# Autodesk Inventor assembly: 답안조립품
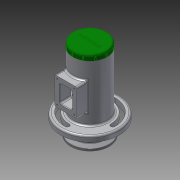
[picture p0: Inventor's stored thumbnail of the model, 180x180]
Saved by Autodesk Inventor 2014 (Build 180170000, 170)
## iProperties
Created: 2017-05
Part Number: 답안조립품
Document SubType Name: Assembly
Designer: Administrator
Author: Administrator
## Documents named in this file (17)
- C:\Users\Administrator\Desktop\470507V1005\답안조립품.iam
- C:\Users\Administrator\Desktop\470507V1005\본체.ipt
- C:\Users\Administrator\Desktop\470507V1005\축.ipt
- C:\Users\Administrator\Desktop\470507V1005\베어링 15 x 35 x 11.ipt
- C:\Users\Administrator\Desktop\470507V1005\부시1.ipt
- C:\Users\Administrator\Desktop\470507V1005\멈춤링 35x1.6.ipt
- C:\Users\Administrator\Desktop\470507V1005\멈춤링 15 x 1.ipt
- C:\Users\Administrator\Desktop\470507V1005\부시2.ipt
- C:\Users\Administrator\Desktop\470507V1005\와셔 10x21.ipt
- C:\Users\Administrator\Desktop\470507V1005\너트 M10.ipt
- C:\Users\Administrator\Desktop\470507V1005\사이드 커버.ipt
- 사이드 커버.ipt
- C:\Users\Administrator\Desktop\470507V1005\키 4 x 4 x 18.ipt
- C:\Users\Administrator\Desktop\470507V1005\V-벨트풀리.ipt
- C:\Users\Administrator\Desktop\470507V1005\와셔 4x16.ipt
- C:\Users\Administrator\Desktop\470507V1005\볼트 M4 x 10.ipt
- C:\Users\Administrator\Desktop\470507V1005\오일 실 15 25 7.ipt
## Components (2 placed, 2 different names)
1. V-벨트풀리:1
2. ISO 4017 M4 x 10:1
